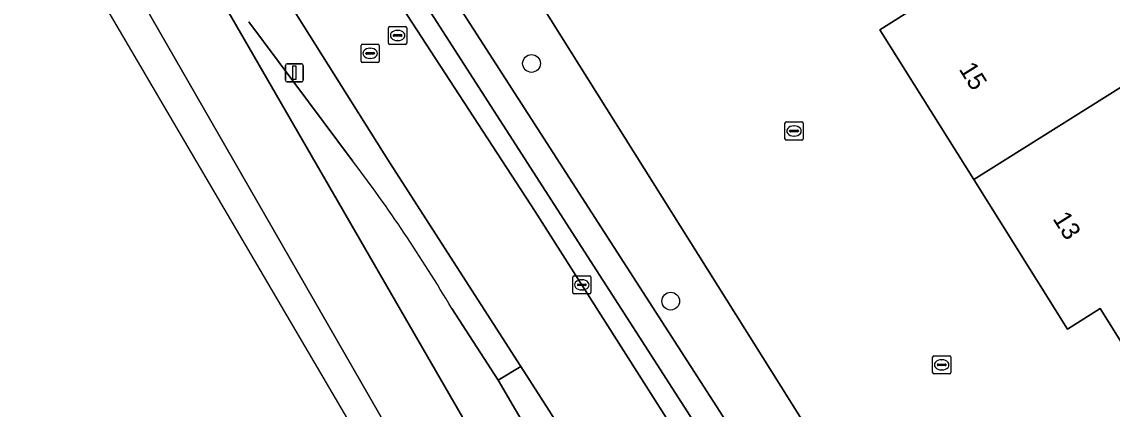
# Model space of a CAD drawing. Extents: x 158455 to 159797, y 387218 to 388672.
# Drawn here: x 158510.1 to 158570.2, y 387717.8 to 387739.1 of the extents above; entities that cross this region are included whole.
import ezdxf

# ---------------------------------------------------------------- set-up
doc = ezdxf.new("R2010")
doc.units = 0
for name, color, linetype in [('IMGEO_Berm_groen', 7, 'Continuous'), ('IMGEO_Boom', 7, 'Continuous'), ('IMGEO_Brandkraan', 7, 'Continuous'), ('IMGEO_Kolk', 7, 'Continuous'), ('IMGEO_Lichtmast', 7, 'Continuous'), ('IMGEO_Pand', 7, 'Continuous'), ('IMGEO_Pand_nummerreeks', 7, 'Continuous'), ('IMGEO_Rijbaan_lokaal_open', 7, 'Continuous'), ('IMGEO_Rijbaan_regionaal_gesloten', 7, 'Continuous'), ('IMGEO_Rioolput', 7, 'Continuous'), ('IMGEO_Voetpad_open', 7, 'Continuous')]:
    doc.layers.add(name, color=color, linetype=linetype)

msp = doc.modelspace()

# ---------------------------------------------------------------- linework, layer by layer
at = {"layer": 'IMGEO_Berm_groen'}
for points in [[(158490.254, 387825.218), (158489.044, 387827.172), (158488.184, 387829.067), (158487.671, 387828.745), (158485, 387824.221), (158484.237, 387821.378), (158506.024, 387783.964), (158509.758, 387777.954), (158515.06, 387769.897), (158527.238, 387750.747), (158548.722, 387717.403), (158561.527, 387695.629), (158567.142, 387685.228), (158568.545, 387685.937), (158571.712, 387687.537), (158533.201, 387748.867), (158526.8, 387758.122)], [(158515.06, 387769.897), (158509.758, 387777.954), (158506.024, 387783.964), (158484.237, 387821.378), (158483.961, 387820.346), (158485.074, 387816.76), (158488.697, 387810.722), (158500, 387791.321), (158504.739, 387783.19), (158508.513, 387777.116), (158508.527, 387777.094), (158525.962, 387750), (158547.445, 387716.616)], [(158560.214, 387694.903), (158565.803, 387684.551), (158567.142, 387685.228), (158561.527, 387695.629), (158548.722, 387717.403), (158527.238, 387750.747), (158515.06, 387769.897)], [(158533.786, 387723.339), (158536.345, 387719.385), (158537.595, 387720.136), (158530.38, 387731.358), (158520.176, 387747.57)], [(158522.602, 387739.12), (158528.321, 387731.472)]]:
    msp.add_lwpolyline(points, dxfattribs=at)
msp.add_arc((158459.759, 387679.499), 86.035, 30.63479, 37.16376, dxfattribs=at)
at = {"layer": 'IMGEO_Boom'}
for centre in [(158538.181, 387736.827), (158545.85, 387723.74)]:
    msp.add_circle(centre, 0.489, dxfattribs=at)
at = {"layer": 'IMGEO_Brandkraan'}
for p, q in [((158528.791, 387736.957), (158528.791, 387737.809)), ((158528.866, 387737.883), (158529.718, 387737.883)), ((158529.279, 387737.663), (158529.304, 387737.663)), ((158529.792, 387737.809), (158529.792, 387736.957)), ((158529.05, 387737.377), (158529.05, 387737.389)), ((158529.488, 387737.34), (158529.09, 387737.34)), ((158529.093, 387737.426), (158529.491, 387737.426)), ((158529.302, 387737.103), (158529.277, 387737.103)), ((158529.534, 387737.389), (158529.534, 387737.377)), ((158529.718, 387736.883), (158528.866, 387736.883))]:
    msp.add_line(p, q, dxfattribs=at)
for points in [[(158528.791, 387736.957), (158528.791, 387737.809)], [(158528.866, 387737.883), (158529.718, 387737.883)], [(158529.792, 387737.809), (158529.792, 387736.957)], [(158529.718, 387736.883), (158528.866, 387736.883)]]:
    msp.add_lwpolyline(points, dxfattribs=at)
for centre, radius, start, end in [((158528.868, 387737.807), 0.0765, 91.55205, 178.44795), ((158528.868, 387737.807), 0.0765, 91.55205, 178.44795), ((158529.716, 387737.807), 0.0765, 1.55205, 88.44795), ((158529.716, 387737.807), 0.0765, 1.55205, 88.44795), ((158529.09, 387737.386), 0.0403, 85.87752, 175.75265), ((158529.087, 387737.376), 0.0366, 178.93798, 274.71019), ((158529.491, 387737.383), 0.043, 264.86636, 352.45326), ((158529.495, 387737.388), 0.0386, 1.73085, 96.63898), ((158528.868, 387736.959), 0.0765, 181.55205, 268.44795), ((158528.868, 387736.959), 0.0765, 181.55205, 268.44795), ((158529.716, 387736.959), 0.0765, 271.55205, 358.44795), ((158529.716, 387736.959), 0.0765, 271.55205, 358.44795)]:
    msp.add_arc(centre, radius, start, end, dxfattribs=at)
for centre, major_axis, ratio, start_param, end_param in [((158529.278, 387737.383), (-0.387, 0.002), 0.722429, 4.712389, 7.853982), ((158529.303, 387737.383), (-0.39, 0.002), 0.717154, 1.570796, 4.712389)]:
    msp.add_ellipse(centre, major_axis=major_axis, ratio=ratio, start_param=start_param, end_param=end_param, dxfattribs=at)
at = {"layer": 'IMGEO_Kolk'}
for p, q in [((158552.144, 387732.682), (158552.144, 387733.534)), ((158552.219, 387733.608), (158553.071, 387733.608)), ((158552.632, 387733.388), (158552.657, 387733.388)), ((158553.145, 387733.534), (158553.145, 387732.682)), ((158552.403, 387733.102), (158552.403, 387733.114)), ((158552.841, 387733.065), (158552.443, 387733.065)), ((158552.446, 387733.151), (158552.844, 387733.151)), ((158552.655, 387732.828), (158552.63, 387732.828)), ((158552.887, 387733.114), (158552.887, 387733.102)), ((158553.071, 387732.608), (158552.219, 387732.608)), ((158540.455, 387724.209), (158540.455, 387725.061)), ((158540.53, 387725.135), (158541.382, 387725.135)), ((158541.456, 387725.061), (158541.456, 387724.209)), ((158540.714, 387724.629), (158540.714, 387724.641)), ((158541.152, 387724.592), (158540.754, 387724.592)), ((158540.757, 387724.678), (158541.155, 387724.678)), ((158540.943, 387724.915), (158540.968, 387724.915)), ((158541.198, 387724.641), (158541.198, 387724.629)), ((158541.382, 387724.135), (158540.53, 387724.135)), ((158540.966, 387724.355), (158540.941, 387724.355)), ((158560.281, 387719.806), (158560.281, 387720.658)), ((158560.356, 387720.732), (158561.208, 387720.732)), ((158560.54, 387720.226), (158560.54, 387720.238)), ((158560.978, 387720.189), (158560.58, 387720.189)), ((158560.583, 387720.275), (158560.981, 387720.275)), ((158560.769, 387720.512), (158560.794, 387720.512)), ((158561.024, 387720.238), (158561.024, 387720.226)), ((158561.282, 387720.658), (158561.282, 387719.806)), ((158561.208, 387719.732), (158560.356, 387719.732)), ((158560.792, 387719.952), (158560.767, 387719.952))]:
    msp.add_line(p, q, dxfattribs=at)
for points in [[(158552.144, 387732.682), (158552.144, 387733.534)], [(158552.219, 387733.608), (158553.071, 387733.608)], [(158553.145, 387733.534), (158553.145, 387732.682)], [(158553.071, 387732.608), (158552.219, 387732.608)], [(158540.455, 387724.209), (158540.455, 387725.061)], [(158540.53, 387725.135), (158541.382, 387725.135)], [(158541.456, 387725.061), (158541.456, 387724.209)], [(158541.382, 387724.135), (158540.53, 387724.135)], [(158560.281, 387719.806), (158560.281, 387720.658)], [(158560.356, 387720.732), (158561.208, 387720.732)], [(158561.282, 387720.658), (158561.282, 387719.806)], [(158561.208, 387719.732), (158560.356, 387719.732)]]:
    msp.add_lwpolyline(points, dxfattribs=at)
for centre, radius, start, end in [((158552.221, 387733.532), 0.0765, 91.55205, 178.44795), ((158552.221, 387733.532), 0.0765, 91.55205, 178.44795), ((158553.069, 387733.532), 0.0765, 1.55205, 88.44795), ((158553.069, 387733.532), 0.0765, 1.55205, 88.44795), ((158552.443, 387733.111), 0.0403, 85.87752, 175.75265), ((158552.44, 387733.101), 0.0366, 178.93798, 274.71019), ((158552.844, 387733.108), 0.043, 264.86636, 352.45326), ((158552.848, 387733.113), 0.0386, 1.73085, 96.63898), ((158552.221, 387732.684), 0.0765, 181.55205, 268.44795), ((158552.221, 387732.684), 0.0765, 181.55205, 268.44795), ((158553.069, 387732.684), 0.0765, 271.55205, 358.44795), ((158553.069, 387732.684), 0.0765, 271.55205, 358.44795), ((158540.532, 387725.059), 0.0765, 91.55205, 178.44795), ((158540.532, 387725.059), 0.0765, 91.55205, 178.44795), ((158541.38, 387725.059), 0.0765, 1.55205, 88.44795), ((158541.38, 387725.059), 0.0765, 1.55205, 88.44795), ((158540.754, 387724.638), 0.0403, 85.87752, 175.75265), ((158540.751, 387724.628), 0.0366, 178.93798, 274.71019), ((158541.155, 387724.635), 0.043, 264.86636, 352.45326), ((158541.159, 387724.64), 0.0386, 1.73085, 96.63898), ((158540.532, 387724.211), 0.0765, 181.55205, 268.44795), ((158540.532, 387724.211), 0.0765, 181.55205, 268.44795), ((158541.38, 387724.211), 0.0765, 271.55205, 358.44795), ((158541.38, 387724.211), 0.0765, 271.55205, 358.44795), ((158560.358, 387720.656), 0.0765, 91.55205, 178.44795), ((158560.358, 387720.656), 0.0765, 91.55205, 178.44795), ((158560.58, 387720.235), 0.0403, 85.87752, 175.75265), ((158560.577, 387720.225), 0.0366, 178.93798, 274.71019), ((158560.981, 387720.232), 0.043, 264.86636, 352.45326), ((158560.985, 387720.237), 0.0386, 1.73085, 96.63898), ((158561.206, 387720.656), 0.0765, 1.55205, 88.44795), ((158561.206, 387720.656), 0.0765, 1.55205, 88.44795), ((158560.358, 387719.808), 0.0765, 181.55205, 268.44795), ((158560.358, 387719.808), 0.0765, 181.55205, 268.44795), ((158561.206, 387719.808), 0.0765, 271.55205, 358.44795), ((158561.206, 387719.808), 0.0765, 271.55205, 358.44795)]:
    msp.add_arc(centre, radius, start, end, dxfattribs=at)
for centre, major_axis, ratio, start_param, end_param in [((158552.631, 387733.108), (-0.387, 0.002), 0.722429, 4.712389, 7.853982), ((158552.656, 387733.108), (-0.39, 0.002), 0.717154, 1.570796, 4.712389), ((158540.942, 387724.635), (-0.387, 0.002), 0.722429, 4.712389, 7.853982), ((158540.967, 387724.635), (-0.39, 0.002), 0.717154, 1.570796, 4.712389), ((158560.768, 387720.232), (-0.387, 0.002), 0.722429, 4.712389, 7.853982), ((158560.793, 387720.232), (-0.39, 0.002), 0.717154, 1.570796, 4.712389)]:
    msp.add_ellipse(centre, major_axis=major_axis, ratio=ratio, start_param=start_param, end_param=end_param, dxfattribs=at)
at = {"layer": 'IMGEO_Lichtmast'}
for p, q in [((158524.617, 387735.913), (158524.617, 387736.713)), ((158524.617, 387736.713), (158524.617, 387735.913)), ((158524.717, 387736.813), (158525.507, 387736.813)), ((158525.507, 387736.813), (158524.717, 387736.813)), ((158525.607, 387736.713), (158525.607, 387735.913)), ((158525.607, 387735.913), (158525.607, 387736.713)), ((158525.507, 387735.813), (158524.717, 387735.813)), ((158524.717, 387735.813), (158525.507, 387735.813))]:
    msp.add_line(p, q, dxfattribs=at)
msp.add_lwpolyline([(158525.037, 387736.688), (158525.187, 387736.688), (158525.187, 387735.938), (158525.037, 387735.938), (158525.037, 387736.688)], dxfattribs=at)
for centre, start, end in [((158524.717, 387736.713), 90, 180), ((158524.717, 387736.713), 90, 180), ((158525.507, 387736.713), 0, 90), ((158525.507, 387736.713), 360, 90), ((158524.717, 387735.913), 180, 270), ((158524.717, 387735.913), 180, 270), ((158525.507, 387735.913), 270, 0), ((158525.507, 387735.913), 270, 0)]:
    msp.add_arc(centre, 0.1, start, end, dxfattribs=at)
at = {"layer": 'IMGEO_Pand'}
for points in [[(158556.592, 387744.011), (158559.218, 387739.828), (158557.375, 387738.671), (158562.544, 387730.436), (158588.976, 387747.022), (158587.107, 387750), (158581.147, 387759.496), (158566.089, 387750)], [(158594.623, 387742.468), (158592.623, 387741.212), (158588.976, 387747.022), (158562.544, 387730.436), (158567.712, 387722.202), (158569.52, 387723.337), (158572.167, 387719.121), (158598.807, 387735.799)]]:
    msp.add_lwpolyline(points, close=True, dxfattribs=at)
at = {"layer": 'IMGEO_Rijbaan_lokaal_open'}
for points in [[(158606.512, 387795.408), (158536.155, 387751.508), (158536.521, 387750.934), (158533.201, 387748.867), (158571.712, 387687.537), (158600.856, 387641.123)], [(158577.568, 387708.434), (158571.23, 387718.533), (158572.167, 387719.121), (158569.52, 387723.337), (158567.712, 387722.202), (158562.544, 387730.436), (158557.375, 387738.671), (158559.218, 387739.828), (158556.592, 387744.011), (158555.708, 387743.457), (158551.601, 387750), (158547.073, 387757.215), (158572.545, 387773.202), (158581.147, 387759.496), (158587.107, 387750), (158588.976, 387747.022), (158592.623, 387741.212), (158594.623, 387742.468), (158595.291, 387742.887), (158593.946, 387745.03), (158590.827, 387750), (158585.81, 387757.993), (158577.633, 387771.021), (158602.63, 387786.71)], [(158547.996, 387713.568), (158538.38, 387728.68), (158527.667, 387745.113), (158524.561, 387750), (158515.055, 387764.958), (158507.961, 387776.157), (158505.768, 387774.768), (158512.445, 387759.315), (158512.984, 387758.448), (158515.849, 387754.329), (158520.176, 387747.57), (158530.38, 387731.358), (158537.595, 387720.136), (158538.221, 387719.162), (158539.142, 387717.73), (158542.411, 387712.569), (158544.544, 387709.112), (158544.581, 387709.051), (158546.395, 387706.11), (158550.048, 387699.701), (158555.986, 387689.308), (158558.845, 387684.197), (158569.244, 387665.018)]]:
    msp.add_lwpolyline(points, dxfattribs=at)
at = {"layer": 'IMGEO_Rijbaan_regionaal_gesloten'}
for points in [[(158514.4, 387751.946), (158510.939, 387758.288), (158508.177, 387761.763), (158489.694, 387792.973), (158477.923, 387812.186), (158475.146, 387810.445), (158483.583, 387796.737), (158495.552, 387776.889), (158507.655, 387756.047), (158516.02, 387741.498), (158522.207, 387730.738), (158531.024, 387715.403), (158537.295, 387704.498), (158545.402, 387690.397), (158555.919, 387672.106), (158568.845, 387649.844)], [(158568.845, 387649.844), (158555.919, 387672.106), (158545.402, 387690.397), (158537.295, 387704.498), (158531.024, 387715.403), (158522.207, 387730.738), (158516.02, 387741.498), (158507.655, 387756.047), (158495.552, 387776.889), (158483.583, 387796.737), (158475.146, 387810.445), (158473.207, 387809.229), (158493.992, 387775.205), (158586.262, 387618.117)], [(158515.744, 387749.684), (158515.79, 387749.53), (158565.676, 387663.212), (158557.959, 387680.586)], [(158565.676, 387663.212), (158515.79, 387749.53), (158515.744, 387749.684)], [(158528.321, 387731.472), (158522.602, 387739.12)], [(158542.893, 387708.174), (158536.345, 387719.385), (158533.786, 387723.339)]]:
    msp.add_lwpolyline(points, dxfattribs=at)
msp.add_arc((158459.759, 387679.499), 86.035, 30.63479, 37.16376, dxfattribs=at)
at = {"layer": 'IMGEO_Rioolput'}
for p, q in [((158530.304, 387737.944), (158530.304, 387738.796)), ((158530.379, 387738.87), (158531.231, 387738.87)), ((158531.305, 387738.796), (158531.305, 387737.944)), ((158530.563, 387738.364), (158530.563, 387738.376)), ((158531.001, 387738.327), (158530.603, 387738.327)), ((158530.606, 387738.413), (158531.004, 387738.413)), ((158530.792, 387738.65), (158530.817, 387738.65)), ((158531.047, 387738.376), (158531.047, 387738.364)), ((158531.231, 387737.87), (158530.379, 387737.87)), ((158530.815, 387738.09), (158530.79, 387738.09))]:
    msp.add_line(p, q, dxfattribs=at)
for points in [[(158530.304, 387737.944), (158530.304, 387738.796)], [(158530.379, 387738.87), (158531.231, 387738.87)], [(158531.305, 387738.796), (158531.305, 387737.944)], [(158531.231, 387737.87), (158530.379, 387737.87)]]:
    msp.add_lwpolyline(points, dxfattribs=at)
for centre, radius, start, end in [((158530.381, 387738.794), 0.0765, 91.55205, 178.44795), ((158530.381, 387738.794), 0.0765, 91.55205, 178.44795), ((158531.229, 387738.794), 0.0765, 1.55205, 88.44795), ((158531.229, 387738.794), 0.0765, 1.55205, 88.44795), ((158530.603, 387738.373), 0.0403, 85.87752, 175.75265), ((158530.6, 387738.363), 0.0366, 178.93798, 274.71019), ((158531.004, 387738.37), 0.043, 264.86636, 352.45326), ((158531.008, 387738.375), 0.0386, 1.73085, 96.63898), ((158530.381, 387737.946), 0.0765, 181.55205, 268.44795), ((158530.381, 387737.946), 0.0765, 181.55205, 268.44795), ((158531.229, 387737.946), 0.0765, 271.55205, 358.44795), ((158531.229, 387737.946), 0.0765, 271.55205, 358.44795)]:
    msp.add_arc(centre, radius, start, end, dxfattribs=at)
for centre, major_axis, ratio, start_param, end_param in [((158530.791, 387738.37), (-0.387, 0.002), 0.722429, 4.712389, 7.853982), ((158530.816, 387738.37), (-0.39, 0.002), 0.717154, 1.570796, 4.712389)]:
    msp.add_ellipse(centre, major_axis=major_axis, ratio=ratio, start_param=start_param, end_param=end_param, dxfattribs=at)
at = {"layer": 'IMGEO_Voetpad_open'}
for points in [[(158547.445, 387716.616), (158525.962, 387750), (158508.527, 387777.094), (158508.513, 387777.116), (158504.739, 387783.19), (158500, 387791.321), (158488.697, 387810.722), (158485.074, 387816.76), (158483.961, 387820.346), (158484.237, 387821.378), (158485, 387824.221), (158487.671, 387828.745), (158488.184, 387829.067), (158487.022, 387830.231)], [(158483.565, 387817.298), (158485.048, 387814.702), (158493.586, 387799.98), (158498.845, 387790.928), (158500, 387789.02), (158504.092, 387782.258), (158504.386, 387781.795), (158507.961, 387776.157), (158515.055, 387764.958), (158524.561, 387750), (158527.667, 387745.113), (158538.38, 387728.68), (158547.996, 387713.568)]]:
    msp.add_lwpolyline(points, dxfattribs=at)
msp.add_lwpolyline([(158539.142, 387717.73), (158538.221, 387719.162), (158537.595, 387720.136), (158536.345, 387719.385), (158542.893, 387708.174), (158543.955, 387708.777), (158544.544, 387709.112), (158542.411, 387712.569)], close=True, dxfattribs=at)

# ---------------------------------------------------------------- texts
at = {"layer": 'IMGEO_Pand_nummerreeks'}
for s, rotation, p in [('15', 302.11594, (158561.703, 387736.516)), ('13', 302.11409, (158566.871, 387728.282))]:
    msp.add_text(s, height=1, rotation=rotation, dxfattribs=at).set_placement(p)

doc.saveas('drawing.dxf')
